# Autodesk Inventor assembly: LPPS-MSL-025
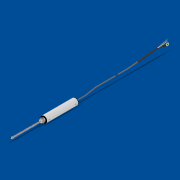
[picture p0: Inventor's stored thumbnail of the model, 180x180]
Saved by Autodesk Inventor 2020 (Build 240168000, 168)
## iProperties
Created: 2019-07
Part Number: LPPS-MSL-025
Document SubType Name: Assembly
Designer: J. Nielson
Author: J. Nielson
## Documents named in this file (5)
- D:\Users\Justin\Documents\CAD Drawings\The Sensor Connection\LPPS\LPPS-MSL\3D\LPPS-MSL-050\LPPS-MSL-050.iam
- D:\Users\Justin\Documents\CAD Drawings\The Sensor Connection\LPPS\LPPS-MSL\3D\LPPS-MSL-050\LPPS-MSL-050 HOUSING_SW.ipt
- D:\Users\Justin\Documents\CAD Drawings\The Sensor Connection\LPPS\LPPS-MSL\3D\LPPS-MSL-050\LPPS-MSL-050 SHAFT_SW.ipt
- D:\Users\Justin\Documents\CAD Drawings\The Sensor Connection\LPPS\LPPS-MSL\3D\MSL PARTS\ISO 4035 - M8BS EN.ipt
- D:\Users\Justin\Documents\CAD Drawings\The Sensor Connection\LPPS\LPPS-MSL\3D\LPPS-MSL-050\LPPS-MSL-050 Spring.ipt
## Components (4 placed, 4 different names)
1. LPPS-MSL-050 HOUSING_SW:1 — Mate:1, Stroke, Mate:3, Flush:1
2. LPPS-MSL-050 SHAFT_SW:1 — Mate:1, Stroke, Angle:5
3. ISO 4035 - M8BS EN:1 — Mate:3, Angle:1, Flush:1
4. LPPS-MSL-050 Spring:1 — Flush:2
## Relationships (7: Mate 3, Angle 2, Flush 2)
- Mate:1: LPPS-MSL-050 HOUSING_SW:1 ↔ LPPS-MSL-050 SHAFT_SW:1
- Stroke [Mate]: LPPS-MSL-050 HOUSING_SW:1 ↔ LPPS-MSL-050 SHAFT_SW:1
- Mate:3: LPPS-MSL-050 HOUSING_SW:1 ↔ ISO 4035 - M8BS EN:1
- Angle:1: ISO 4035 - M8BS EN:1
- Flush:1: LPPS-MSL-050 HOUSING_SW:1 ↔ ISO 4035 - M8BS EN:1
- Flush:2: LPPS-MSL-050 Spring:1
- Angle:5: LPPS-MSL-050 SHAFT_SW:1
